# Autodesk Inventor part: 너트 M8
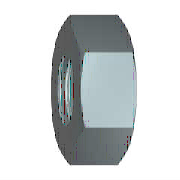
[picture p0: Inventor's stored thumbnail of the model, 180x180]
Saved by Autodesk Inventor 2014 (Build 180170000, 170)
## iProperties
IsCustomPart: 1
Created: 2012-02
Part Number: 너트 M8
Material: 강철, 연강
Description: 6각 너트
Document SubType Name: Modeling
Standard: KS B 1012
Designer: mduedu
Standards Organization: KS
Language: ko-KR
Size Designation: M8
Categories: <MemberInstance><Categories><Category DisplayName="조임쇠" InternalName="e4da775c-781d-43d5-af7c-5136215cf5a6" Mnemonic="FSTN"><Category DisplayName="너트" InternalN
Density: 1 g/cm^3
Appearance: 강철
Author: mduedu
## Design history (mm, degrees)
sketch "스케치1"
  geometry: L1 (-7.506, 0)-(-3.753, 6.5); L2 (-3.753, 6.5)-(3.753, 6.5); L3 (3.753, 6.5)-(7.506, 0); L4 (7.506, 0)-(3.753, -6.5); L5 (3.753, -6.5)-(-3.753, -6.5); L6 (-3.753, -6.5)-(-7.506, 0); 2 further points
  constraints: 12 end point, 1 coincident, 1 horizontal, 11 other
  dimensions: "d0" = 15.01111 distance of L3.end L1.start (= 1.1547 x SW)
extrude "본체" new body sketch "스케치1" distance "d1" = 5 (= KOH); taper "d2" = 0 deg
sketch "스케치2"
  geometry: L1 (0, 3.753)-(0, 7.506) reference; L2 (0, 7.506)-(5, 7.506) reference; L3 (5, 3.753)-(5, 7.506) reference; L4 (-1, 0)-(6, 0) reference; L5 (0.581, 7.506)-(0, 6.5); L6 (4.419, 7.506)-(5, 6.5)
  constraints: 4 end point, 4 point on line
  dimensions: "d3" = 30 deg angle of L1 L5 (= ANG1); "d4" = 30 deg angle of L3 L6 (= ANG2); "d5" = 13 diameter of L5.end L4 (= SW0); "d6" = 13 diameter of L6.end L4 (= SW01)
revolve "모따기1" sketch "스케치2" stored, may be unused: angle "d7" = 90 deg
sketch "스케치3"
  geometry: A1 r 6.5 centre (0, 0) between (-3.25, -5.629) and (3.25, -5.629) reference; 1 further point
  constraints: 1 coincident
hole "스레드" sketch "스케치3" at (0, 0) diameter "d25" = 6.647; stored, may be unused: countersink angle "d29" = 82 deg, drill point angle "d31" = 118 deg; dims "d26" = 6, "d27" = 4, "d28" = 2, "d30" = 8
workaxis "Work Axis1"
workplane "Work Plane1"
body "Solid1"
chamfer "모따기2" distance "d8" = 0.67658 (= -0.5 x GD1 + 0.5 x NND); stored, may be unused: angle "d9" = 30 deg, second distance "d40" = 0.67658 (= -0.5 x GD1 + 0.5 x NND)
chamfer "모따기3" distance "d10" = 0.67658 (= -0.5 x GD1 + 0.5 x NND); stored, may be unused: angle "d11" = 30 deg, second distance "d41" = 0.67658 (= -0.5 x GD1 + 0.5 x NND)
other parameters: "ANG1" = 30 deg [user parameter; used in 1 equation term], "ANG2" = 30 deg [user parameter; used in 1 equation term], "NND" = 8 [user parameter; used in 4 equation terms], "KOH" = 5 [user parameter; used in 1 equation term], "SW" = 13 [user parameter; used in 4 equation terms], "SW0" = 13 (= SW) [user parameter; used in 1 equation term], "SW01" = 13 (= SW) [user parameter; used in 1 equation term], "GD1" = 6.64684 (computed from THREADDIA, PTC, TOA) [user parameter; used in 4 equation terms], "d13" = 0, "d14" = 0, "d39" = 0, "d42" = 0, "GUL" = 0.67658 (= 0.541266 x PTC) [user parameter], "TPU" = 8 (computed from PTC) [user parameter], "THREADDIA" = 8 [user parameter; used in 1 equation term], "TOA" = 30 deg [user parameter; used in 1 equation term], "PTC" = 1.25 [user parameter; used in 4 equation terms], "E0" = 15.015 (= 1.155 x SW) [user parameter], "GAL" = 0.67658 (= 0.541266 x PTC) [user parameter]
